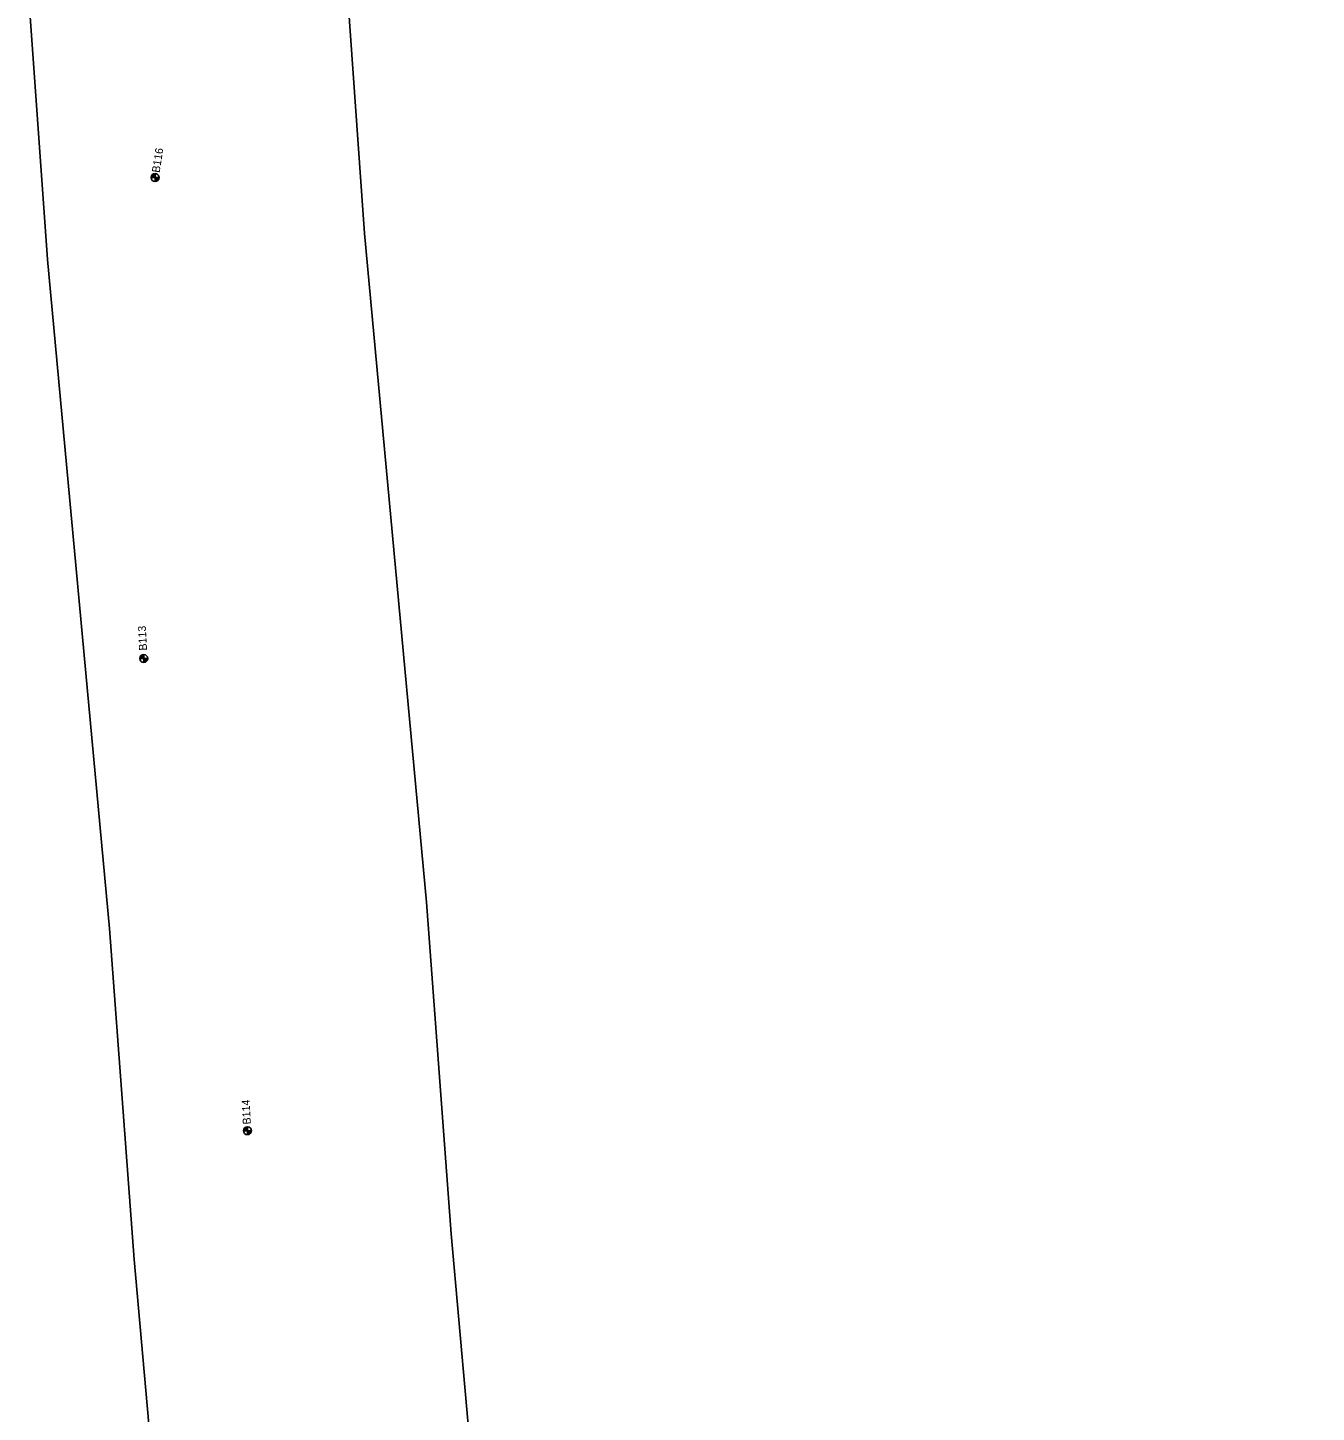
# Model space of a CAD drawing. Extents: x 327762 to 372792, y 127949 to 259367.
# Drawn here: x 355040 to 356660, y 190437 to 192178 of the extents above; entities that cross this region are included whole.
import ezdxf

# ---------------------------------------------------------------- set-up
doc = ezdxf.new("R2010")
doc.units = 0
for name, color, linetype in [('E_SOIL_BORE1 [KAPUR_CADDS_LEVELS]', 7, 'Continuous'), ('E_SOIL_BORE2 [KAPUR_CADDS_LEVELS]', 7, 'Continuous'), ('P_MARK', 7, 'Continuous'), ('P_TC', 7, 'Continuous')]:
    doc.layers.add(name, color=color, linetype=linetype)

msp = doc.modelspace()

# ---------------------------------------------------------------- linework, layer by layer
at = {"layer": 'P_MARK'}
for p, q in [((355195.5, 191989.3), (355205.5, 191989.3)), ((355200.5, 191994.3), (355200.5, 191984.3)), ((355181.3, 191384.7), (355191.3, 191384.7)), ((355186.3, 191389.7), (355186.3, 191379.7)), ((355311.6, 190791.1), (355321.6, 190791.1)), ((355316.6, 190796.1), (355316.6, 190786.1))]:
    msp.add_line(p, q, dxfattribs=at)
for centre in [(355200.5, 191989.3), (355186.3, 191384.7), (355316.6, 190791.1)]:
    msp.add_circle(centre, 5, dxfattribs=at)
for centre, radius, start, end in [((355200.5, 191989.3), 4.5, 89.9869, 179.9869), ((355200.5, 191989.3), 4, 89.9869, 179.9869), ((355200.5, 191989.3), 3.5, 89.9869, 179.9869), ((355200.5, 191989.3), 3, 89.9869, 179.9869), ((355200.5, 191989.3), 2.5, 89.9869, 179.9869), ((355200.5, 191989.3), 2, 89.9869, 179.9869), ((355200.5, 191989.3), 1.5, 89.9869, 179.9869), ((355200.5, 191989.3), 1, 89.9869, 179.9869), ((355200.5, 191989.3), 0.5, 89.9869, 179.9869), ((355200.5, 191989.3), 4.5, 269.9869, 359.9869), ((355200.5, 191989.3), 4, 269.9869, 359.9869), ((355200.5, 191989.3), 3.5, 269.9869, 359.9869), ((355200.5, 191989.3), 3, 269.9869, 359.9869), ((355200.5, 191989.3), 2.5, 269.9869, 359.9869), ((355200.5, 191989.3), 2, 269.9869, 359.9869), ((355200.5, 191989.3), 1.5, 269.9869, 359.9869), ((355200.5, 191989.3), 1, 269.9869, 359.9869), ((355200.5, 191989.3), 0.5, 269.9869, 359.9869), ((355186.3, 191384.7), 4.5, 89.9869, 179.9869), ((355186.3, 191384.7), 4, 89.9869, 179.9869), ((355186.3, 191384.7), 3.5, 89.9869, 179.9869), ((355186.3, 191384.7), 3, 89.9869, 179.9869), ((355186.3, 191384.7), 2.5, 89.9869, 179.9869), ((355186.3, 191384.7), 2, 89.9869, 179.9869), ((355186.3, 191384.7), 1.5, 89.9869, 179.9869), ((355186.3, 191384.7), 1, 89.9869, 179.9869), ((355186.3, 191384.7), 0.5, 89.9869, 179.9869), ((355186.3, 191384.7), 4.5, 269.9869, 359.9869), ((355186.3, 191384.7), 4, 269.9869, 359.9869), ((355186.3, 191384.7), 3.5, 269.9869, 359.9869), ((355186.3, 191384.7), 3, 269.9869, 359.9869), ((355186.3, 191384.7), 2.5, 269.9869, 359.9869), ((355186.3, 191384.7), 2, 269.9869, 359.9869), ((355186.3, 191384.7), 1.5, 269.9869, 359.9869), ((355186.3, 191384.7), 1, 269.9869, 359.9869), ((355186.3, 191384.7), 0.5, 269.9869, 359.9869), ((355316.6, 190791.1), 4.5, 89.9869, 179.9869), ((355316.6, 190791.1), 4, 89.9869, 179.9869), ((355316.6, 190791.1), 3.5, 89.9869, 179.9869), ((355316.6, 190791.1), 3, 89.9869, 179.9869), ((355316.6, 190791.1), 2.5, 89.9869, 179.9869), ((355316.6, 190791.1), 2, 89.9869, 179.9869), ((355316.6, 190791.1), 1.5, 89.9869, 179.9869), ((355316.6, 190791.1), 1, 89.9869, 179.9869), ((355316.6, 190791.1), 0.5, 89.9869, 179.9869), ((355316.6, 190791.1), 4.5, 269.9869, 359.9869), ((355316.6, 190791.1), 4, 269.9869, 359.9869), ((355316.6, 190791.1), 3.5, 269.9869, 359.9869), ((355316.6, 190791.1), 3, 269.9869, 359.9869), ((355316.6, 190791.1), 2.5, 269.9869, 359.9869), ((355316.6, 190791.1), 2, 269.9869, 359.9869), ((355316.6, 190791.1), 1.5, 269.9869, 359.9869), ((355316.6, 190791.1), 1, 269.9869, 359.9869), ((355316.6, 190791.1), 0.5, 269.9869, 359.9869)]:
    msp.add_arc(centre, radius, start, end, dxfattribs=at)
at = {"layer": 'P_TC'}
for points in [[(355283.6, 189224), (355274.3, 189348.2), (355249.7, 189692.4), (355212.6, 190196.5), (355174, 190629), (355143, 191045.2), (355065.1, 191886.3), (355040.4, 192233.4), (355074.6, 192700.4), (355130.4, 193038.8), (355243.3, 193407.8), (355370.8, 193719.1), (355556, 194116.5), (355747.6, 194472.4), (355922.8, 194827.6), (356106.3, 195206.2), (356289.3, 195658.8)], [(356660.1, 195508.9), (356472.1, 195043.8), (356282.2, 194652), (356103.2, 194289), (355913.6, 193937), (355737.4, 193558.7), (355620.5, 193273.2), (355520.7, 192947.3), (355472.2, 192653.1), (355441.4, 192233), (355463.8, 191918.9), (355541.6, 191078.5), (355572.6, 190661.6), (355611.3, 190229), (355648.6, 189721.3), (355673.2, 189377.4), (355691.8, 189129.9)]]:
    msp.add_lwpolyline(points, dxfattribs=at)

# ---------------------------------------------------------------- texts
at = {"layer": 'E_SOIL_BORE1 [KAPUR_CADDS_LEVELS]'}
msp.add_text('B114', height=10, rotation=93.0065, dxfattribs=at).set_placement((355320.9, 190799.2))
at = {"layer": 'E_SOIL_BORE2 [KAPUR_CADDS_LEVELS]'}
for s, rotation, p in [('B116', 80.9358, (355206.1, 191994.8)), ('B113', 93.0065, (355190.4, 191394.9))]:
    msp.add_text(s, height=10, rotation=rotation, dxfattribs=at).set_placement(p)

doc.saveas('drawing.dxf')
